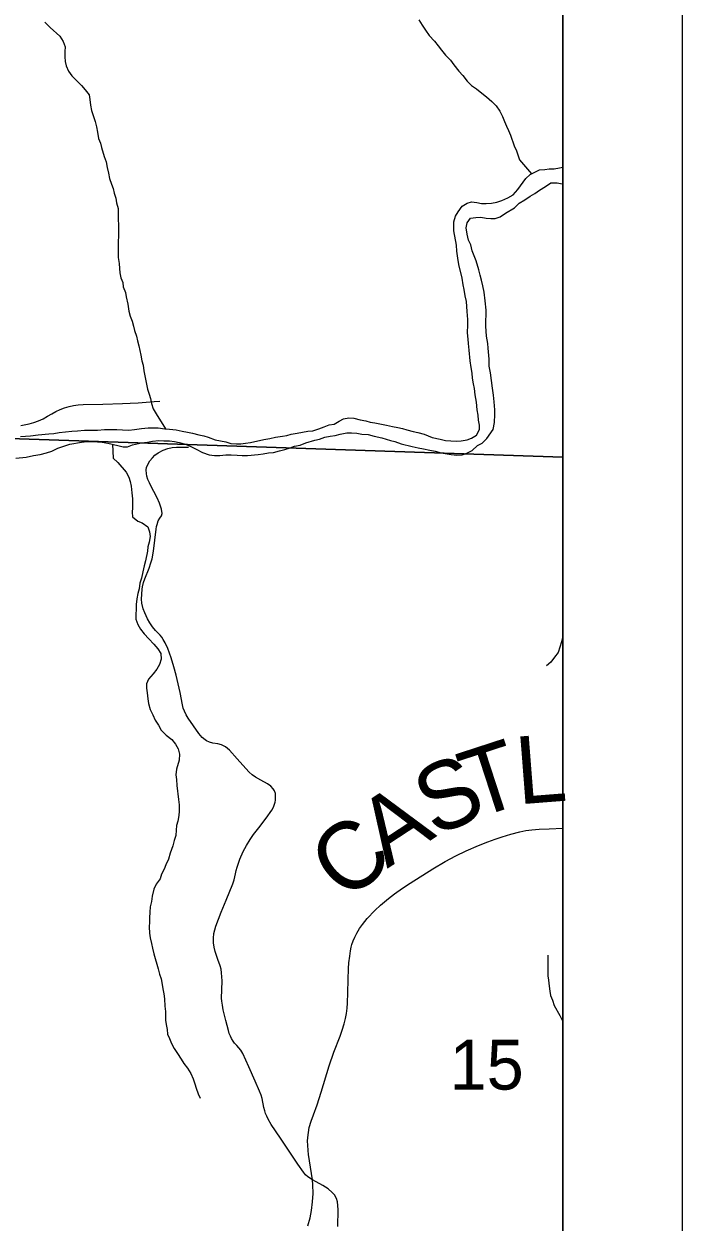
# Model space of a CAD drawing. Extents: x -7.9 to 76.1, y 0 to 22.
# Drawn here: x 8.447 to 9, y 14.511 to 15.518 of the extents above; entities that cross this region are included whole.
import ezdxf

# ---------------------------------------------------------------- set-up
doc = ezdxf.new("R2010")
doc.units = 0
for name, color, linetype in [('GM_X_County_Road', 7, 'Continuous'), ('GM_X_County_Road_Text', 7, 'Continuous'), ('GM_X_Major_River', 7, 'Continuous'), ('GM_X_Minor_River', 7, 'Continuous'), ('GM_X_Section_Text', 7, 'Continuous'), ('GM_X_Township_Road', 7, 'Continuous'), ('SC_Scratch1', 7, 'Continuous'), ('SH_Data', 7, 'Continuous')]:
    doc.layers.add(name, color=color, linetype=linetype)

msp = doc.modelspace()

# ---------------------------------------------------------------- linework, layer by layer
at = {"layer": 'GM_X_County_Road'}
for points in [[(8.6896, 14.5467), (8.6871, 14.5626), (8.6864, 14.5679), (8.686, 14.5714), (8.6857, 14.5759), (8.6856, 14.5793), (8.6857, 14.5824), (8.6862, 14.5866), (8.6869, 14.5907), (8.6885, 14.5961), (8.6904, 14.6014), (8.6935, 14.6098), (8.697, 14.6204), (8.7038, 14.6425), (8.7076, 14.6539), (8.7129, 14.6673), (8.7147, 14.6725), (8.7162, 14.6777), (8.7175, 14.6823), (8.7183, 14.6864), (8.7189, 14.6908), (8.7192, 14.6951), (8.7194, 14.7041), (8.7196, 14.7147), (8.7199, 14.7243), (8.7203, 14.7289), (8.7209, 14.7346), (8.7216, 14.739), (8.7222, 14.742), (8.7227, 14.7445), (8.7237, 14.7474), (8.7251, 14.7506), (8.7268, 14.7538), (8.7292, 14.7577), (8.7316, 14.7611), (8.7357, 14.7663), (8.7421, 14.773), (8.7469, 14.7775), (8.7534, 14.783), (8.7585, 14.7869), (8.7653, 14.7916), (8.7716, 14.7958), (8.7908, 14.8078), (8.8012, 14.814), (8.81, 14.8188), (8.8186, 14.823), (8.8292, 14.8275), (8.8369, 14.8306), (8.8432, 14.8329), (8.849, 14.8349), (8.8562, 14.8371), (8.8637, 14.839), (8.8688, 14.84), (8.8738, 14.8407), (8.8799, 14.8412), (8.8884, 14.8416), (8.9, 14.8421)], [(8.6859, 14.5082), (8.6876, 14.5149), (8.6889, 14.5211), (8.6898, 14.5282), (8.6902, 14.5351), (8.6901, 14.5425), (8.6896, 14.5467)]]:
    msp.add_lwpolyline(points, dxfattribs=at)
at = {"layer": 'GM_X_Major_River'}
for points in [[(8.7298, 15.1849), (8.7344, 15.1842), (8.7382, 15.1831), (8.742, 15.1824), (8.7462, 15.1817), (8.7519, 15.1806), (8.7568, 15.1795), (8.7614, 15.1785), (8.7652, 15.1778), (8.769, 15.1767), (8.7743, 15.1752), (8.7781, 15.1745), (8.7834, 15.1731), (8.7903, 15.1702), (8.7968, 15.1687), (8.8013, 15.1677), (8.8059, 15.1673), (8.8108, 15.167), (8.8146, 15.1675), (8.8195, 15.1683), (8.8233, 15.1695), (8.8274, 15.1722), (8.83, 15.1768), (8.83, 15.1806), (8.8292, 15.1847), (8.8287, 15.1889), (8.8279, 15.1935), (8.8274, 15.1999), (8.8262, 15.206), (8.8258, 15.2113), (8.825, 15.2154), (8.8241, 15.22), (8.8237, 15.2241), (8.8229, 15.2291), (8.822, 15.2347), (8.8212, 15.2434), (8.8207, 15.2491), (8.8203, 15.2529), (8.8198, 15.2582), (8.8201, 15.2647), (8.8201, 15.2692), (8.8196, 15.2761), (8.8191, 15.2844), (8.8179, 15.2893), (8.8171, 15.2946), (8.8162, 15.2984), (8.8154, 15.3041), (8.8126, 15.3154), (8.8118, 15.3207), (8.8109, 15.3268), (8.8105, 15.3317), (8.8084, 15.3438), (8.8083, 15.3514), (8.8098, 15.356), (8.812, 15.3598), (8.8154, 15.3644), (8.8195, 15.3671), (8.8233, 15.368), (8.8278, 15.3676), (8.8316, 15.3666), (8.8354, 15.3666), (8.84, 15.367), (8.8445, 15.3679), (8.8487, 15.3691), (8.8536, 15.3714), (8.8581, 15.3741), (8.8622, 15.3784), (8.8689, 15.3876), (8.8726, 15.391), (8.8802, 15.3949), (8.8847, 15.3954), (8.8885, 15.3958), (8.8927, 15.3959), (8.8972, 15.3967), (8.9, 15.3972)], [(8.6528, 15.1572), (8.657, 15.1576), (8.6619, 15.1589), (8.6664, 15.1601), (8.671, 15.1616), (8.6747, 15.1628), (8.6793, 15.1637), (8.6842, 15.1656), (8.6917, 15.168), (8.6955, 15.1688), (8.7, 15.1704), (8.7046, 15.1712), (8.7087, 15.172), (8.7129, 15.1729), (8.7186, 15.1741), (8.7224, 15.1741), (8.7269, 15.1738), (8.7311, 15.1731), (8.7364, 15.1728), (8.7414, 15.1714), (8.7478, 15.1699), (8.7551, 15.1678), (8.7589, 15.1667), (8.7642, 15.1649), (8.7733, 15.1627), (8.7783, 15.1616), (8.7828, 15.1606), (8.7882, 15.1595), (8.7927, 15.1588), (8.7977, 15.1574), (8.806, 15.156), (8.811, 15.1553), (8.8155, 15.1557), (8.8193, 15.1569), (8.8238, 15.1592), (8.8283, 15.1635), (8.8321, 15.1654), (8.8362, 15.1693), (8.8414, 15.1769), (8.8425, 15.1827), (8.8427, 15.1895), (8.8427, 15.1933), (8.8422, 15.2001), (8.8418, 15.2058), (8.8409, 15.2115), (8.8392, 15.2244), (8.838, 15.23), (8.8379, 15.2361), (8.8371, 15.2452), (8.837, 15.249), (8.8358, 15.2554), (8.8354, 15.2596), (8.8353, 15.2638), (8.8352, 15.2683), (8.8355, 15.2733), (8.8355, 15.277), (8.8346, 15.285), (8.8338, 15.2922), (8.8326, 15.2975), (8.8317, 15.3024), (8.8305, 15.3066), (8.8294, 15.3111), (8.827, 15.3187), (8.8238, 15.327), (8.8226, 15.3319), (8.8207, 15.336), (8.8195, 15.341), (8.8186, 15.3463), (8.8197, 15.3504), (8.8223, 15.3543), (8.8269, 15.3551), (8.831, 15.3552), (8.8356, 15.3545), (8.8394, 15.3541), (8.8432, 15.3542), (8.8473, 15.3554), (8.8518, 15.3585), (8.8594, 15.3631), (8.8631, 15.367), (8.868, 15.3697), (8.8725, 15.3728), (8.8763, 15.3751), (8.8804, 15.3779), (8.8853, 15.381), (8.8898, 15.3841), (8.8951, 15.3841), (8.8993, 15.3831), (8.9, 15.3829)], [(8.4444, 15.171), (8.4528, 15.1715), (8.4592, 15.1723), (8.4683, 15.1732), (8.4725, 15.1736), (8.477, 15.1745), (8.4876, 15.1754), (8.4922, 15.1758), (8.4982, 15.1763), (8.5092, 15.1764), (8.5149, 15.1769), (8.5255, 15.177), (8.5301, 15.1767), (8.5354, 15.1764), (8.5403, 15.1769), (8.546, 15.1777), (8.5517, 15.1782), (8.56, 15.1783), (8.5657, 15.1776), (8.5695, 15.1773), (8.5752, 15.1766), (8.5801, 15.1755), (8.5847, 15.1748), (8.5889, 15.1738), (8.5942, 15.1723), (8.5984, 15.1716), (8.6022, 15.1705), (8.6079, 15.1683), (8.6125, 15.1673), (8.617, 15.1666), (8.6212, 15.1651), (8.6258, 15.1648), (8.6296, 15.1648), (8.6334, 15.1653), (8.6375, 15.1661), (8.6489, 15.1685), (8.6538, 15.1694), (8.6587, 15.1706), (8.6644, 15.1714), (8.6682, 15.1718), (8.6719, 15.173), (8.6769, 15.1739), (8.6859, 15.1755), (8.6901, 15.1759), (8.695, 15.1775), (8.6995, 15.1791), (8.7037, 15.1807), (8.7079, 15.1815), (8.712, 15.1838), (8.7158, 15.1858), (8.7203, 15.1866), (8.7245, 15.1863), (8.7298, 15.1849)], [(8.4405, 15.1527), (8.4492, 15.1536), (8.4553, 15.1552), (8.461, 15.156), (8.4662, 15.1572), (8.4708, 15.1588), (8.4757, 15.1612), (8.4817, 15.1631), (8.4859, 15.1647), (8.4957, 15.1664), (8.5002, 15.1668), (8.5052, 15.1669), (8.509, 15.1666), (8.5131, 15.1662), (8.5177, 15.1655), (8.5261, 15.1634), (8.5306, 15.1623), (8.5344, 15.1624), (8.5386, 15.1639), (8.5461, 15.1656), (8.5511, 15.1664), (8.5552, 15.1672), (8.5605, 15.1677), (8.5647, 15.1673), (8.5696, 15.1674), (8.5738, 15.1667), (8.5776, 15.166), (8.5829, 15.1646), (8.5875, 15.1627), (8.5921, 15.1605), (8.5974, 15.1576), (8.6028, 15.1557), (8.6073, 15.155), (8.6119, 15.1551), (8.6168, 15.1556), (8.6214, 15.1556), (8.6263, 15.1553), (8.6305, 15.155), (8.635, 15.1551), (8.6441, 15.1559), (8.6483, 15.1564), (8.6528, 15.1572)]]:
    msp.add_lwpolyline(points, dxfattribs=at)
at = {"layer": 'GM_X_Minor_River'}
for points in [[(8.4648, 15.5189), (8.4694, 15.5144), (8.4774, 15.5073), (8.4802, 15.5028), (8.4821, 15.4982), (8.4818, 15.4945), (8.4818, 15.4899), (8.4819, 15.4861), (8.4827, 15.4823), (8.4847, 15.4778), (8.4877, 15.474), (8.4916, 15.4699), (8.4958, 15.4658), (8.4989, 15.4621), (8.502, 15.4579), (8.5028, 15.4541), (8.5033, 15.4492), (8.5041, 15.4447), (8.5057, 15.4398), (8.5072, 15.4356), (8.5084, 15.4311), (8.5092, 15.4265)], [(8.7791, 15.521), (8.7818, 15.5165), (8.7845, 15.5124), (8.7876, 15.5079), (8.7922, 15.503), (8.7953, 15.4992), (8.798, 15.4955), (8.8015, 15.4914), (8.8057, 15.4872), (8.8084, 15.4831), (8.8127, 15.4779), (8.8158, 15.4741), (8.8196, 15.4696), (8.8231, 15.4659), (8.8273, 15.4629), (8.8319, 15.4595), (8.8357, 15.4562), (8.8403, 15.4524), (8.8438, 15.4487), (8.8469, 15.4442), (8.8492, 15.4397), (8.8508, 15.4355), (8.8527, 15.4317), (8.8543, 15.428), (8.8559, 15.4242), (8.859, 15.4151), (8.861, 15.411), (8.8634, 15.4034), (8.8735, 15.3915)], [(8.5092, 15.4265), (8.5101, 15.4212), (8.5116, 15.4174), (8.5125, 15.4137), (8.5148, 15.4061), (8.5164, 15.4016), (8.5172, 15.397), (8.5184, 15.3921), (8.5193, 15.3876), (8.5208, 15.383), (8.5224, 15.3793), (8.5232, 15.3755), (8.5244, 15.3713), (8.5252, 15.3672), (8.5264, 15.3626), (8.5267, 15.3395), (8.5264, 15.3345), (8.5266, 15.3213), (8.5274, 15.3163), (8.5275, 15.3122), (8.5279, 15.3084), (8.5287, 15.3042), (8.5303, 15.3004), (8.5307, 15.2967), (8.5327, 15.2921), (8.5331, 15.2883), (8.5347, 15.2823), (8.5355, 15.2762), (8.5367, 15.2721), (8.5383, 15.2679), (8.5395, 15.2638), (8.5403, 15.26), (8.5419, 15.2554), (8.5427, 15.2513), (8.5439, 15.2471), (8.5447, 15.2433), (8.5455, 15.2392), (8.5464, 15.2346), (8.5475, 15.2309), (8.548, 15.2263), (8.5488, 15.2221), (8.5512, 15.2108), (8.5524, 15.2066), (8.5536, 15.2029), (8.5544, 15.1987), (8.556, 15.1942), (8.5583, 15.19), (8.5663, 15.1776)], [(8.5218, 15.1645), (8.5224, 15.1527), (8.5263, 15.1493), (8.5332, 15.1411), (8.5355, 15.137), (8.5367, 15.1332), (8.5375, 15.1294), (8.538, 15.1237), (8.5384, 15.1188), (8.5385, 15.1112), (8.5382, 15.1074), (8.5386, 15.1036), (8.5429, 15.0999), (8.5467, 15.0984), (8.5513, 15.0951), (8.5528, 15.0909), (8.5533, 15.0871), (8.5526, 15.0822), (8.5515, 15.0784), (8.5512, 15.0746), (8.5494, 15.0666), (8.5483, 15.0624), (8.5472, 15.0574), (8.5462, 15.0521), (8.5447, 15.0479), (8.544, 15.043), (8.5429, 15.0391), (8.5422, 15.0346), (8.5415, 15.03), (8.5416, 15.0262), (8.5413, 15.0213), (8.5413, 15.0175), (8.5429, 15.013), (8.5452, 15.0092), (8.5483, 15.0054), (8.5522, 15.001), (8.5564, 14.9965), (8.5599, 14.9927), (8.5622, 14.9889), (8.5626, 14.984), (8.5612, 14.9794), (8.5589, 14.9756), (8.556, 14.9718), (8.5519, 14.9672), (8.5504, 14.9634), (8.5504, 14.9596), (8.5509, 14.9558), (8.5513, 14.9508), (8.5521, 14.9467), (8.5533, 14.9418), (8.5557, 14.9372), (8.5576, 14.9327), (8.5603, 14.9286), (8.5627, 14.9244), (8.5669, 14.9203), (8.5715, 14.9166), (8.5746, 14.9125), (8.5769, 14.9087), (8.5781, 14.9042), (8.5778, 14.8992), (8.5756, 14.8916), (8.5749, 14.887), (8.5754, 14.8829), (8.5758, 14.878), (8.5771, 14.8662), (8.5776, 14.8617), (8.5776, 14.8564), (8.5773, 14.8526), (8.5766, 14.848), (8.5755, 14.8442), (8.5752, 14.8404), (8.5749, 14.8358), (8.5734, 14.8316), (8.5723, 14.8271), (8.5701, 14.821), (8.5687, 14.816), (8.5665, 14.8114), (8.565, 14.8076), (8.5628, 14.8034), (8.5617, 14.7996), (8.5584, 14.795), (8.5565, 14.7908), (8.5551, 14.7851), (8.5544, 14.7805), (8.5533, 14.7759), (8.553, 14.7714), (8.5527, 14.7668), (8.5527, 14.763), (8.5524, 14.7592), (8.5528, 14.7539), (8.5533, 14.7501), (8.5545, 14.7452), (8.5553, 14.7414), (8.5565, 14.7365), (8.5601, 14.724), (8.5613, 14.7195), (8.5625, 14.7154), (8.5633, 14.7108), (8.5641, 14.707), (8.5649, 14.7029), (8.5653, 14.6987)], [(8.9, 15.0035), (8.8999, 15.0028), (8.8988, 14.9986), (8.8959, 14.9895), (8.8929, 14.9857), (8.8899, 14.9814), (8.8862, 14.9784)], [(8.8872, 14.7355), (8.8874, 14.7181), (8.8878, 14.7143), (8.8883, 14.7094), (8.8891, 14.7052), (8.8895, 14.7014), (8.8911, 14.6976), (8.8927, 14.6931), (8.8973, 14.6848), (8.9, 14.6797)], [(8.5653, 14.6987), (8.5658, 14.6926), (8.5662, 14.6881), (8.5663, 14.6809), (8.5668, 14.6771), (8.5676, 14.6729), (8.568, 14.6691), (8.5696, 14.6654), (8.5712, 14.6612), (8.5735, 14.6571), (8.5762, 14.6529), (8.5793, 14.648), (8.5816, 14.6443), (8.5847, 14.6405), (8.5874, 14.636), (8.5894, 14.6315), (8.591, 14.6273), (8.5921, 14.6236), (8.5937, 14.619), (8.5953, 14.6153)]]:
    msp.add_lwpolyline(points, dxfattribs=at)
at = {"layer": 'GM_X_Township_Road'}
for points in [[(8.4448, 15.1803), (8.4476, 15.1808), (8.4517, 15.1817), (8.4557, 15.1829), (8.4596, 15.1843), (8.4634, 15.186), (8.4671, 15.188), (8.4707, 15.1901), (8.4742, 15.192), (8.4778, 15.1937), (8.4815, 15.1951), (8.4853, 15.1962), (8.4891, 15.1971), (8.493, 15.1977), (8.497, 15.198), (8.5137, 15.1983), (8.53, 15.1987), (8.5367, 15.1989), (8.5434, 15.1993), (8.55, 15.1998), (8.5567, 15.2004), (8.5614, 15.2008)], [(8.5513, 15.1472), (8.5517, 15.1481), (8.5532, 15.1507), (8.5552, 15.153), (8.5574, 15.1553), (8.56, 15.1572), (8.5643, 15.1595), (8.5683, 15.161), (8.5718, 15.1618), (8.5754, 15.1621), (8.5855, 15.1621)], [(8.7109, 14.5076), (8.7111, 14.5216), (8.711, 14.5252), (8.7106, 14.5282), (8.7097, 14.5311), (8.7081, 14.5342), (8.7063, 14.5361), (8.7027, 14.5392), (8.6983, 14.542), (8.6896, 14.5467), (8.6858, 14.5493), (8.6839, 14.551), (8.682, 14.5531), (8.6774, 14.5598), (8.6718, 14.5683), (8.6629, 14.5816), (8.655, 14.5933), (8.6525, 14.5977), (8.6512, 14.6003), (8.6503, 14.6024), (8.6497, 14.6046), (8.6488, 14.6076), (8.6473, 14.6149), (8.6465, 14.6178), (8.6453, 14.6211), (8.6415, 14.6297), (8.6362, 14.6416), (8.6311, 14.6528), (8.6296, 14.6555), (8.6278, 14.6577), (8.626, 14.6595), (8.6243, 14.6615), (8.6231, 14.6631), (8.6216, 14.6655), (8.6207, 14.6673), (8.6198, 14.6695), (8.6191, 14.6722), (8.617, 14.6806), (8.6148, 14.6894), (8.6141, 14.6934), (8.6136, 14.6967), (8.6134, 14.6994), (8.6135, 14.7063), (8.6137, 14.7138), (8.6134, 14.7207), (8.6129, 14.7236), (8.6121, 14.7264), (8.6102, 14.7317), (8.6084, 14.7369), (8.6079, 14.7384), (8.6071, 14.7421), (8.6066, 14.7459), (8.6065, 14.7497), (8.6069, 14.7535), (8.6076, 14.7568), (8.6085, 14.7598), (8.6129, 14.7714), (8.6171, 14.7816), (8.6229, 14.7954), (8.6239, 14.7987), (8.6251, 14.8038), (8.6256, 14.8064), (8.6263, 14.8094), (8.6287, 14.8159), (8.6315, 14.8225), (8.6342, 14.8276), (8.6372, 14.8325), (8.6402, 14.8367), (8.6445, 14.8424), (8.6508, 14.8505), (8.6554, 14.8573), (8.6568, 14.8598), (8.6579, 14.8622), (8.6584, 14.8639), (8.6587, 14.8657), (8.6585, 14.8712), (8.6579, 14.8734), (8.6567, 14.8752), (8.6548, 14.8773), (8.6519, 14.8792), (8.6464, 14.8825), (8.6418, 14.885), (8.639, 14.8869), (8.6366, 14.8891), (8.6312, 14.8951), (8.6265, 14.9004), (8.6201, 14.9077), (8.6166, 14.9103), (8.6154, 14.911), (8.6132, 14.9121), (8.6101, 14.913), (8.6061, 14.9136), (8.6033, 14.9143), (8.6007, 14.9155), (8.5995, 14.9162), (8.597, 14.9182), (8.5943, 14.9217), (8.5852, 14.9346), (8.5835, 14.9374), (8.5821, 14.9404), (8.5812, 14.9429), (8.5804, 14.9456), (8.5785, 14.9559), (8.577, 14.9632), (8.5752, 14.9707), (8.5733, 14.9776), (8.571, 14.9851), (8.5681, 14.9931), (8.566, 14.9977), (8.5644, 15.0004), (8.5631, 15.0024), (8.5618, 15.0041), (8.5595, 15.0065), (8.5578, 15.0081), (8.5554, 15.0111), (8.5531, 15.0145), (8.5511, 15.0179), (8.5489, 15.0228), (8.5476, 15.0264), (8.5464, 15.0311), (8.5461, 15.0344), (8.5466, 15.0427), (8.547, 15.0448), (8.5479, 15.0484), (8.549, 15.0516), (8.5526, 15.0604), (8.554, 15.0648), (8.5549, 15.0682), (8.5561, 15.0746), (8.5584, 15.0933), (8.5586, 15.0953), (8.5591, 15.0971), (8.5602, 15.1001), (8.5616, 15.1025), (8.5628, 15.1045), (8.5633, 15.1063), (8.5629, 15.1101), (8.5612, 15.1149), (8.5592, 15.1194), (8.5565, 15.1247), (8.5539, 15.1296), (8.5527, 15.1321), (8.5515, 15.135), (8.5507, 15.1377), (8.5502, 15.14), (8.55, 15.1428), (8.5504, 15.1453), (8.5513, 15.1472)]]:
    msp.add_lwpolyline(points, dxfattribs=at)
at = {"layer": 'SC_Scratch1'}
for points in [[(8.9, 15.1537), (8.9, 16.161), (8.2558, 16.1845), (8.2275, 15.1763)], [(8.9, 14.1574), (8.9, 15.1537), (8.2275, 15.1763), (8.1994, 14.1795)]]:
    msp.add_lwpolyline(points, close=True, dxfattribs=at)
at = {"layer": 'SH_Data'}
for p, q in [((9, 21), (9, 14)), ((8.9, 20.9), (8.9, 14.1))]:
    msp.add_line(p, q, dxfattribs=at)

# ---------------------------------------------------------------- texts
at = {"layer": 'GM_X_County_Road_Text'}
for s, rotation, p in [('T', 18.0663, (8.8255, 14.8495)), ('L', 4.4465, (8.8624, 14.862)), ('S', 24.444, (8.7922, 14.8342)), ('A', 33.2006, (8.7524, 14.8079)), ('C', 39.7366, (8.7179, 14.7791))]:
    msp.add_text(s, height=0.0568, rotation=rotation, dxfattribs=at).set_placement(p)
at = {"layer": 'GM_X_Section_Text'}
msp.add_text('15', height=0.04186, rotation=0, dxfattribs=at).set_placement((8.8048, 14.6225))

doc.saveas('drawing.dxf')
